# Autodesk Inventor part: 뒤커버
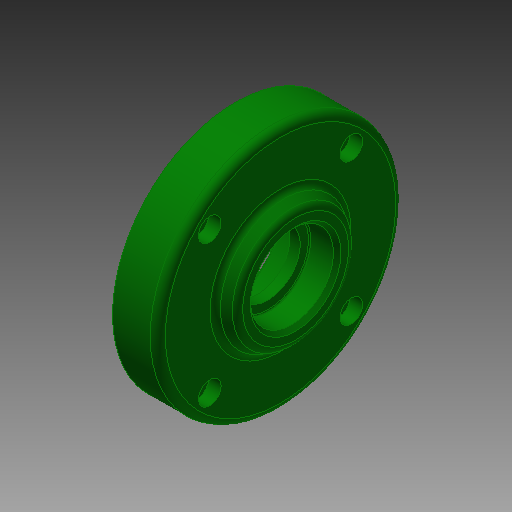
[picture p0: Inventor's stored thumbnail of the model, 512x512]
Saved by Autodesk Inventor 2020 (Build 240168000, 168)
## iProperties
Created: 2015-12
Part Number: 뒤커버
Document SubType Name: Modeling
Designer: mdu
Density: 2.71 g/cm^3
Mass: 97.9591 g
Surface Area: 115.525 cm^2
Volume: 36.1473 cm^3
Material: 알루미늄-6061
Appearance: 진녹색
Company: 한국ATC센터
Author: mdu
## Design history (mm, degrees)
sketch "스케치1"
  geometry: L1 (-10.5, 0)-(10.5, 0); L2 (10.5, 0)-(10.5, 22.5); L3 (10.5, 22.5)-(5.5, 22.5); L4 (5.5, 22.5)-(5.5, 32.5); L5 (5.5, 32.5)-(-6.5, 32.5); L6 (-6.5, 32.5)-(-6.5, 17.5); L7 (-6.5, 17.5)-(-10.5, 15.191); L8 (-10.5, 15.191)-(-10.5, 0); 2 further points
  constraints: 16 end point, 3 parallel, 3 perpendicular, 1 coincident, 1 horizontal, 1 midpoint
  dimensions: "d0" = 21 distance of L1.start L1.end; "d1" = 65 diameter of L5 L1; "d2" = 45 diameter of L3 L1; "d3" = 35 diameter of L6.end L1; "d4" = 120 deg angle of L7 L6; "d5" = 12 distance of L4.end L5.end; "d6" = 5 distance of L2.end L3.end
revolve "회전1" sketch "스케치1" stored, may be unused: angle "d7" = 90 deg
sketch "스케치2"
  geometry: L1 (0, 0)-(32.5, 0); L2 (0, 0)-(18.738, 18.738); 1 further point
  constraints: 4 end point, 1 horizontal, 1 horizontal alignment, 1 other
  dimensions: "d8" = 45 deg angle of L1 L2; "d9" = 26.5 distance of L1.start L2.end
hole "구멍1" sketch "스케치2" at (18.738, 18.738) diameter "d10" = 3.4; stored, may be unused: countersink angle "d14" = 90 deg, drill point angle "d16" = 118 deg; dims "d11" = 6, "d12" = 6, "d13" = 3.3, "d15" = 8
fillet "모깎기1" dims "d20" = 2
hole "구멍2" diameter "d23" = 15; stored, may be unused: countersink angle "d27" = 90 deg, drill point angle "d29" = 0 deg; dims "d21" = 10, "d22" = 10, "d24" = 6, "d25" = 35, "d26" = 11, "d28" = 14
chamfer "모따기1" distance "d39" = 1; stored, may be unused: second distance "d40" = 2, angle "d41" = 45 deg
fillet "모깎기2" dims "d42" = 0.3
hole "구멍4" diameter "d46" = 17; stored, may be unused: countersink angle "d50" = 90 deg, drill point angle "d52" = 118 deg; dims "d44" = 10, "d45" = 10, "d47" = 6, "d48" = 22, "d49" = 7.3, "d51" = 8
chamfer "모따기2" distance "d53" = 1; stored, may be unused: second distance "d54" = 2, angle "d55" = 45 deg
fillet "모깎기3" dims "d56" = 0.3
node "작업 평면1"
sketch "스케치3"
  geometry: 2 further points
  constraints: 1 coincident, 1 other
feature "엠보싱1" sketch "스케치3" dims "d0" = 21, "d1" = 65, "d2" = 45, "d3" = 35, "d4" = 120 deg, "d5" = 12, "d6" = 5, "d58" = 0.3, "d59" = 0
fillet "모깎기4" dims "d60" = 0.2
fillet "모깎기5" dims "d61" = 0.1
node "솔리드1"
pattern_circular "원형 패턴1" dims angle "d18" = 360 deg
